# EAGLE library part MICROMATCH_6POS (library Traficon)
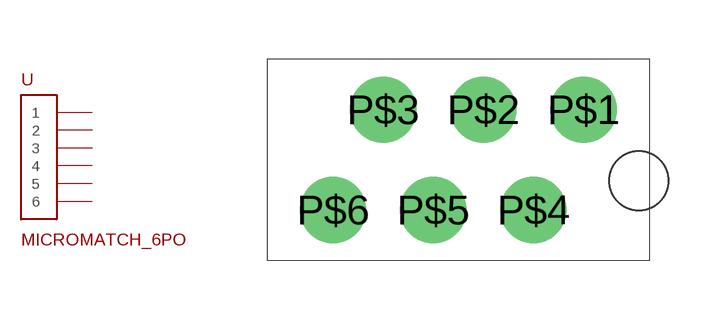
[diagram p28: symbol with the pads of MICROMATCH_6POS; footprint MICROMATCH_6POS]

Designator prefix -

## MICROMATCH_6POS  [MICROMATCH_6POS]
P$1  1
P$2  3
P$3  5
P$4  2
P$5  4
P$6  6

## Footprint MICROMATCH_6POS (pad centres in mm)
drill 0.8 pad 1.676 round: P$1 0,0; P$2 -2.54,0; P$3 -5.08,0; P$4 -1.27,-2.54; P$5 -3.81,-2.54; P$6 -6.35,-2.54
hole 1.5 at 1.4,-1.8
